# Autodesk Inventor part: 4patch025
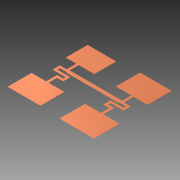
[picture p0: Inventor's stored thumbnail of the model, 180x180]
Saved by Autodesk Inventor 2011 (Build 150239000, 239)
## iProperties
Created: 2014-03
Part Number: 4patch025
Document SubType Name: Modeling
Designer: Evgeny
Density: 1 g/cm^3
Author: Evgeny
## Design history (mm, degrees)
sketch "Эскиз1"
  geometry: L1 (-65, 4.5)-(64.5, 4.5); L2 (64.5, -3)-(64.5, -4.5); L3 (64.5, -4.5)-(-64.5, -4.5); L4 (-64.5, -4.5)-(-64.5, -3); L5 (-71, 3)-(-81.5, 3); L6 (-81.5, -3)-(-64.5, -3); L7 (-71, 3)-(-71, 27); L8 (-71, 27)-(-65, 27); L9 (-65, 27)-(-65, 4.5); L10 (-81.5, 3)-(-87.5, 3); L11 (-87.5, 3)-(-87.5, -14); L12 (-81.5, -9)-(-81.5, -3); L13 (-81.5, -9)-(-49.5, -9); L14 (-49.5, -9)-(-49.5, -25); L15 (-55.5, -15)-(-87.5, -15); L16 (-87.5, -15)-(-87.5, -14); L17 (-55.5, -15)-(-55.5, -21); L18 (-56.5, -27)-(-49.5, -27); L19 (-49.5, -27)-(-49.5, -25); L20 (-56.5, -27)-(-64.5, -27); L21 (-70.5, -37)-(-70.5, -21); L22 (-70.5, -21)-(-55.5, -21); L23 (-70.5, -21)-(-66, -21); L24 (-64.5, -27)-(-64.5, -48); L25 (-64.5, -48)-(-70.5, -48); L26 (-70.5, -48)-(-70.5, -21); L27 (70.5, 3)-(87.5, 3); L28 (87.5, 3)-(87.5, -3); L29 (81.5, -3)-(64.5, -3); L30 (70.5, 3)-(70.5, 27); L31 (70.5, 27)-(64.5, 27); L32 (64.5, 27)-(64.5, 4.5); L33 (81.5, -3)-(81.5, -9); L34 (85.5, -15)-(87.5, -15); L35 (87.5, -15)-(87.5, -3); L36 (85.5, -15)-(55.5, -15); L37 (49.5, -15)-(49.5, -9); L38 (49.5, -9)-(81.5, -9); L39 (49.5, -9)-(55.5, -9); L40 (55.5, -15)-(55.5, -21); L41 (55.5, -27)-(49.5, -27); L42 (49.5, -27)-(49.5, -9); L43 (55.5, -27)-(64.5, -27); L44 (70.5, -27)-(70.5, -21); L45 (70.5, -21)-(55.5, -21); L46 (70.5, -21)-(65, -21); L47 (64.5, -27)-(64.5, -48); L48 (64.5, -48)-(70.5, -48); L49 (70.5, -48)-(70.5, -21); L50 (-97.1, 81)-(-26.5, 81); L51 (-26.5, 81)-(-26.5, 27); L52 (-26.5, 27)-(-97.1, 27); L53 (-97.1, 27)-(-97.1, 81); L54 (26.5, 86.5)-(104.5, 86.5); L55 (104.5, 86.5)-(104.5, 27); L56 (104.5, 27)-(26.5, 27); L57 (26.5, 27)-(26.5, 86.5); L58 (-106.5, -107)-(-25.5, -107); L59 (-25.5, -107)-(-25.5, -48); L60 (-25.5, -48)-(-106.5, -48); L61 (-106.5, -48)-(-106.5, -107); L62 (25.5, -111)-(110.5, -111); L63 (110.5, -111)-(110.5, -48); L64 (110.5, -48)-(25.5, -48)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; 1 further point
  constraints: 130 end point, 28 parallel, 15 horizontal, 14 perpendicular
  dimensions: "d0" = 129 distance between parallel lines of L2 L4; "d1" = 64.5 distance from line of point (0, 0) L4; "d2" = 9 distance between parallel lines of L3 L1; "d3" = 4.5 distance from line of point (0, 0) L3; "d5" = 6 distance between parallel lines of L5 L6; "d6" = 22.5 distance between parallel lines of L8 L1; "d7" = 6 distance between parallel lines of L7 L9; "d8" = 17 distance from line of L4.end L12; "d9" = 6 distance between parallel lines of L11 L12; "d10" = 6 distance between parallel lines of L13 L6; "d11" = 6 distance between parallel lines of L15 L13; "d12" = 15 distance between parallel lines of L19 L24; "d13" = 6 distance between parallel lines of L19 L17; "d14" = 6 distance between parallel lines of L20 L22; "d15" = 6 distance between parallel lines of L26 L24; "d16" = 27 distance between parallel lines of L25 L22; "d17" = 33 distance between parallel lines of L15 L25; "d18" = 64.5 distance from line of L24 point (0, 0); "d19" = 6 distance between parallel lines of L30 L32; "d20" = 17 distance between parallel lines of L33 L2; "d21" = 6 distance between parallel lines of L27 L29; "d22" = 6 distance between parallel lines of L35 L33; "d23" = 6 distance between parallel lines of L36 L38; "d24" = 6 distance between parallel lines of L49 L47; "d25" = 6 distance between parallel lines of L43 L45; "d26" = 6 distance between parallel lines of L42 L40; "d27" = 129 distance between parallel lines of L47 L24; "d28" = 15 distance between parallel lines of L42 L47; "d29" = 33 distance between parallel lines of L36 L48; "d30" = 27 distance between parallel lines of L45 L48; "d31" = 70.6 distance between parallel lines of L53 L51; "d32" = 54 distance between parallel lines of L52 L50; "d33" = 78 distance between parallel lines of L55 L57; "d34" = 59.5 distance between parallel lines of L56 L54; "d35" = 53 distance between parallel lines of L57 L51; "d36" = 26.5 distance from line of L57 point (0, 0); "d37" = 59 distance between parallel lines of L58 L60; "d38" = 81 distance between parallel lines of L59 L61; "d39" = 63 distance between parallel lines of L62 L64; "d40" = 85 distance between parallel lines of L63 L65; "d41" = 51 distance between parallel lines of L65 L59; "d42" = 25.5 distance from line of L59 point (0, 0)
extrude "Выдавливание1" new body sketch "Эскиз1" distance "d43" = 0.25; taper "d44" = 0 deg
node "Твердое тело1"
